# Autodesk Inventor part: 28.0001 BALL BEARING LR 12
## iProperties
Created: 2007-06
Part Number: 28.0001 BALL BEARING LR 12
Document SubType Name: Modeling
Designer: Andy Moles
Material: Steel
Mass: 95.9107 g
Surface Area: 40.8402 cm^2
Volume: 12.2179 cm^3
Density: 7.85 g/cm^3
Author: Andy Moles
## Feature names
1. Revolution1
2. Fillet1
